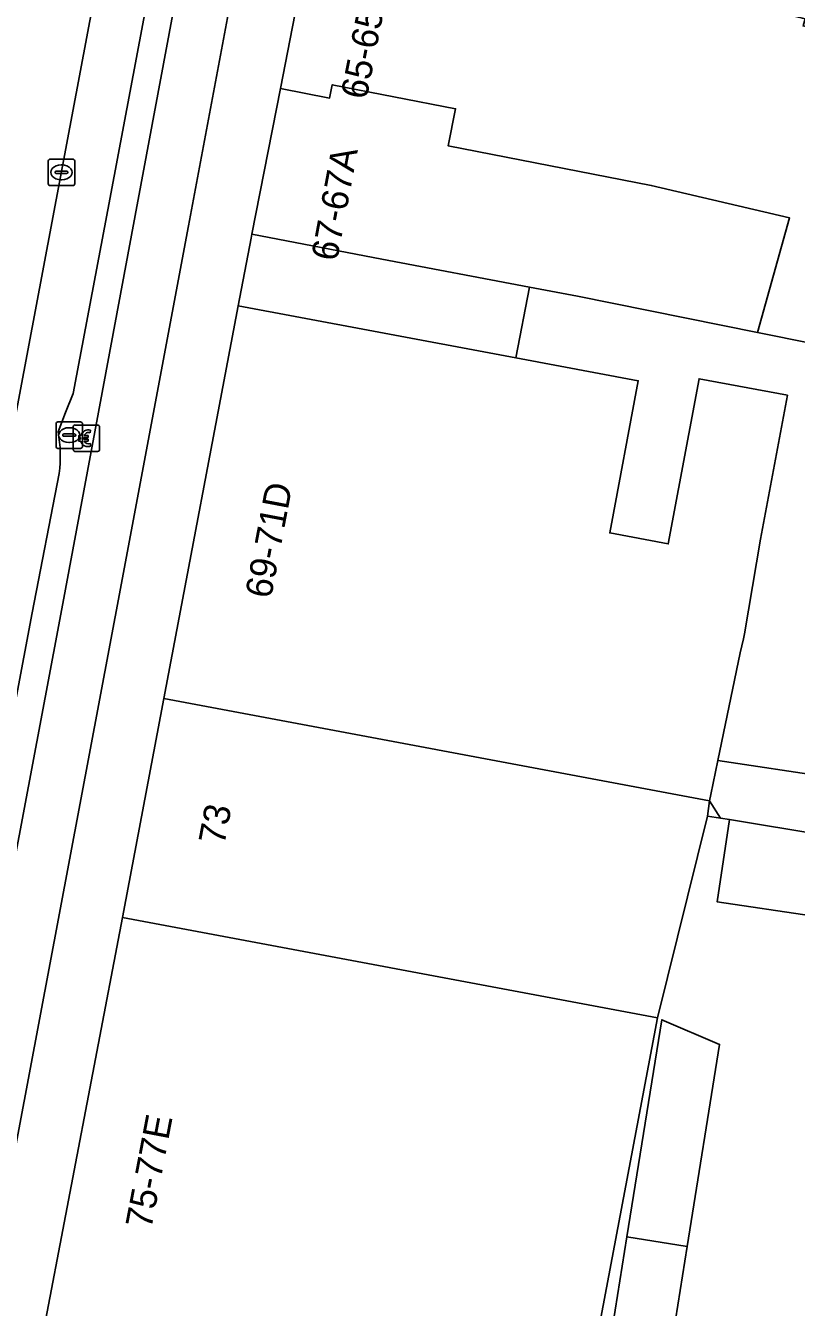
# Model space of a CAD drawing. Extents: x 161838 to 162344, y 381620 to 382160.
# Drawn here: x 161893.72 to 161922.84, y 381857.83 to 381906.27 of the extents above; entities that cross this region are included whole.
import ezdxf

# ---------------------------------------------------------------- set-up
doc = ezdxf.new("R2010")
doc.units = 0
for name, color, linetype in [('IMGEO_Berm_open', 7, 'Continuous'), ('IMGEO_Betaalautomaat', 7, 'Continuous'), ('IMGEO_Brandkraan', 7, 'Continuous'), ('IMGEO_Erf', 7, 'Continuous'), ('IMGEO_Fietspad_gesloten', 7, 'Continuous'), ('IMGEO_Kolk', 7, 'Continuous'), ('IMGEO_Pand', 7, 'Continuous'), ('IMGEO_Pand_nummerreeks', 7, 'Continuous'), ('IMGEO_Pand_overbouw', 7, 'Continuous'), ('IMGEO_Parkeervlak_open', 7, 'Continuous'), ('IMGEO_Rijbaan_lokaal_gesloten', 7, 'Continuous'), ('IMGEO_Voetpad_open', 7, 'Continuous')]:
    doc.layers.add(name, color=color, linetype=linetype)

msp = doc.modelspace()

# ---------------------------------------------------------------- linework, layer by layer
at = {"layer": 'IMGEO_Berm_open'}
for points in [[(161897.858, 381899.101), (161916.698, 382000), (161921.558, 382026.031), (161926.346, 382051.921)], [(161900.616, 381919.482), (161896.821, 381899.305), (161895.517, 381892.371), (161895.218, 381891.646), (161894.941, 381890.914)], [(161857.316, 381682.246), (161862.987, 381712.892), (161864.774, 381722.548), (161869.854, 381750), (161870.207, 381751.91), (161895.081, 381884.229), (161897.858, 381899.101)], [(161894.979, 381889.343), (161893.959, 381884.074), (161881.221, 381816.302), (161880.899, 381815.584)]]:
    msp.add_lwpolyline(points, dxfattribs=at)
msp.add_arc((161890.246, 381890.014), 4.78, 351.925, 10.8462, dxfattribs=at)
at = {"layer": 'IMGEO_Betaalautomaat'}
for p, q in [((161895.511, 381890.252), (161895.511, 381891.093)), ((161895.511, 381891.093), (161895.511, 381890.252)), ((161895.586, 381891.176), (161896.427, 381891.176)), ((161896.427, 381891.176), (161895.586, 381891.176)), ((161896.173, 381890.981), (161896.156, 381890.881)), ((161896.51, 381891.102), (161896.51, 381890.261)), ((161896.51, 381890.261), (161896.51, 381891.102)), ((161895.794, 381890.64), (161895.794, 381890.708)), ((161895.915, 381890.708), (161895.915, 381890.64)), ((161896.16, 381890.475), (161896.182, 381890.388)), ((161896.436, 381890.177), (161895.595, 381890.177)), ((161895.595, 381890.177), (161896.436, 381890.177))]:
    msp.add_line(p, q, dxfattribs=at)
for points in [[(161895.794, 381890.708), (161895.725, 381890.708), (161895.725, 381890.777), (161895.804, 381890.777)], [(161895.799, 381890.571), (161895.725, 381890.571), (161895.725, 381890.64), (161895.794, 381890.64)], [(161895.926, 381890.777), (161896.073, 381890.777), (161896.073, 381890.708), (161895.915, 381890.708)], [(161895.915, 381890.64), (161896.073, 381890.64), (161896.073, 381890.571), (161895.929, 381890.571)]]:
    msp.add_lwpolyline(points, dxfattribs=at)
for centre, radius, start, end in [((161895.589, 381891.099), 0.0779, 92.4484, 184.2845), ((161895.589, 381891.099), 0.0779, 92.4484, 184.2845), ((161896.087, 381890.701), 0.293, 73.014, 165.0139), ((161896.433, 381891.099), 0.0779, 2.4484, 94.2845), ((161896.433, 381891.099), 0.0779, 2.4484, 94.2845), ((161896.06, 381890.626), 0.267, 191.8096, 297.0389), ((161896.093, 381890.714), 0.179, 69.3236, 159.5683), ((161896.093, 381890.641), 0.179, 202.7625, 291.8693), ((161895.589, 381890.255), 0.0779, 182.4484, 274.2845), ((161895.589, 381890.255), 0.0779, 182.4484, 274.2845), ((161896.433, 381890.255), 0.0779, 272.4484, 4.2845), ((161896.433, 381890.255), 0.0779, 272.4484, 4.2845)]:
    msp.add_arc(centre, radius, start, end, dxfattribs=at)
at = {"layer": 'IMGEO_Brandkraan'}
for p, q in [((161894.864, 381890.368), (161894.864, 381891.22)), ((161894.939, 381891.294), (161895.791, 381891.294)), ((161895.352, 381891.074), (161895.377, 381891.074)), ((161895.865, 381891.22), (161895.865, 381890.368)), ((161895.123, 381890.788), (161895.123, 381890.8)), ((161895.561, 381890.751), (161895.163, 381890.751)), ((161895.166, 381890.837), (161895.564, 381890.837)), ((161895.375, 381890.514), (161895.35, 381890.514)), ((161895.607, 381890.8), (161895.607, 381890.788)), ((161895.791, 381890.294), (161894.939, 381890.294))]:
    msp.add_line(p, q, dxfattribs=at)
for points in [[(161894.864, 381890.368), (161894.864, 381891.22)], [(161894.939, 381891.294), (161895.791, 381891.294)], [(161895.865, 381891.22), (161895.865, 381890.368)], [(161895.791, 381890.294), (161894.939, 381890.294)]]:
    msp.add_lwpolyline(points, dxfattribs=at)
for centre, radius, start, end in [((161894.941, 381891.218), 0.0765, 91.552, 178.448), ((161894.941, 381891.218), 0.0765, 91.552, 178.448), ((161895.789, 381891.218), 0.0765, 1.552, 88.448), ((161895.789, 381891.218), 0.0765, 1.552, 88.448), ((161895.163, 381890.797), 0.0403, 85.8775, 175.7526), ((161895.16, 381890.787), 0.0366, 178.938, 274.7102), ((161895.564, 381890.794), 0.043, 264.8664, 352.4533), ((161895.568, 381890.799), 0.0386, 1.7309, 96.639), ((161894.941, 381890.37), 0.0765, 181.552, 268.448), ((161894.941, 381890.37), 0.0765, 181.552, 268.448), ((161895.789, 381890.37), 0.0765, 271.552, 358.448), ((161895.789, 381890.37), 0.0765, 271.552, 358.448)]:
    msp.add_arc(centre, radius, start, end, dxfattribs=at)
for centre, major_axis, ratio, start_param, end_param in [((161895.351, 381890.794), (-0.387, 0.002), 0.722429, 4.712389, 7.853982), ((161895.376, 381890.794), (-0.39, 0.002), 0.717154, 1.570796, 4.712389)]:
    msp.add_ellipse(centre, major_axis=major_axis, ratio=ratio, start_param=start_param, end_param=end_param, dxfattribs=at)
at = {"layer": 'IMGEO_Erf'}
for points in [[(161923.437, 381894.255), (161921.374, 381894.671), (161914.564, 381896.043), (161912.75, 381896.389), (161907.18, 381897.45), (161902.268, 381898.386), (161902.239, 381898.237), (161901.744, 381895.676), (161906.659, 381894.757), (161912.24, 381893.714), (161916.864, 381892.849), (161915.788, 381887.095), (161917.997, 381886.682), (161919.164, 381892.922), (161922.502, 381892.298), (161921.485, 381886.86), (161920.879, 381883.283), (161920.836, 381883.1), (161920.712, 381882.567), (161919.869, 381878.497), (161924.063, 381877.869)], [(161927.341, 381856.208), (161927.586, 381859.394), (161927.862, 381862.975), (161923.927, 381863.278), (161924.192, 381866.576), (161931.915, 381865.948), (161936.898, 381865.542), (161937.059, 381867.638), (161932.115, 381868.378), (161926.43, 381869.229), (161926.861, 381872.114), (161926.008, 381872.241), (161923.414, 381872.627), (161919.842, 381873.159), (161920.308, 381876.262), (161919.974, 381876.316), (161919.486, 381876.396), (161917.589, 381868.765), (161914.902, 381854.491)]]:
    msp.add_lwpolyline(points, dxfattribs=at)
for points in [[(161919.552, 381876.967), (161919.486, 381876.396), (161919.974, 381876.316)], [(161917.918, 381855.141), (161915.635, 381855.508), (161916.435, 381860.485), (161917.755, 381868.694), (161919.938, 381867.762), (161918.709, 381860.12)]]:
    msp.add_lwpolyline(points, close=True, dxfattribs=at)
at = {"layer": 'IMGEO_Fietspad_gesloten'}
for points in [[(161897.095, 381883.929), (161899.866, 381898.705), (161907.39, 381938.834), (161908.427, 381944.469), (161918.786, 382000), (161923.625, 382025.943), (161928.95, 382054.459)], [(161926.346, 382051.921), (161921.558, 382026.031), (161916.698, 382000), (161897.858, 381899.101), (161895.081, 381884.229), (161870.207, 381751.91), (161869.854, 381750), (161864.774, 381722.548), (161862.987, 381712.892), (161857.316, 381682.246)], [(161859.158, 381680.785), (161865.321, 381714.277), (161866.402, 381720.165), (161871.936, 381750), (161872.236, 381751.615), (161897.095, 381883.929)]]:
    msp.add_lwpolyline(points, dxfattribs=at)
at = {"layer": 'IMGEO_Kolk'}
for p, q in [((161894.569, 381900.3), (161894.569, 381901.152)), ((161894.644, 381901.226), (161895.496, 381901.226)), ((161895.57, 381901.152), (161895.57, 381900.3)), ((161894.828, 381900.72), (161894.828, 381900.732)), ((161895.266, 381900.683), (161894.868, 381900.683)), ((161894.871, 381900.769), (161895.269, 381900.769)), ((161895.057, 381901.006), (161895.082, 381901.006)), ((161895.312, 381900.732), (161895.312, 381900.72)), ((161895.496, 381900.226), (161894.644, 381900.226)), ((161895.08, 381900.446), (161895.055, 381900.446))]:
    msp.add_line(p, q, dxfattribs=at)
for points in [[(161894.569, 381900.3), (161894.569, 381901.152)], [(161894.644, 381901.226), (161895.496, 381901.226)], [(161895.57, 381901.152), (161895.57, 381900.3)], [(161895.496, 381900.226), (161894.644, 381900.226)]]:
    msp.add_lwpolyline(points, dxfattribs=at)
for centre, radius, start, end in [((161894.646, 381901.15), 0.0765, 91.552, 178.448), ((161894.646, 381901.15), 0.0765, 91.552, 178.448), ((161895.494, 381901.15), 0.0765, 1.552, 88.448), ((161895.494, 381901.15), 0.0765, 1.552, 88.448), ((161894.868, 381900.729), 0.0403, 85.8775, 175.7526), ((161894.865, 381900.719), 0.0366, 178.938, 274.7102), ((161895.269, 381900.726), 0.043, 264.8664, 352.4533), ((161895.273, 381900.731), 0.0386, 1.7309, 96.639), ((161894.646, 381900.302), 0.0765, 181.552, 268.448), ((161894.646, 381900.302), 0.0765, 181.552, 268.448), ((161895.494, 381900.302), 0.0765, 271.552, 358.448), ((161895.494, 381900.302), 0.0765, 271.552, 358.448)]:
    msp.add_arc(centre, radius, start, end, dxfattribs=at)
for centre, major_axis, ratio, start_param, end_param in [((161895.056, 381900.726), (-0.387, 0.002), 0.722429, 4.712389, 7.853982), ((161895.081, 381900.726), (-0.39, 0.002), 0.717154, 1.570796, 4.712389)]:
    msp.add_ellipse(centre, major_axis=major_axis, ratio=ratio, start_param=start_param, end_param=end_param, dxfattribs=at)
at = {"layer": 'IMGEO_Pand'}
for points in [[(161923.168, 381906.529), (161923.069, 381906.553), (161922.591, 381906.67), (161916.152, 381908.245), (161904.636, 381910.55), (161904.615, 381910.446), (161903.341, 381903.897), (161905.201, 381903.534), (161905.299, 381904.038), (161909.961, 381903.128), (161909.687, 381901.727), (161917.356, 381900.23), (161922.583, 381899.012), (161921.374, 381894.671), (161923.437, 381894.255), (161924.39, 381897.931), (161925.021, 381900.361), (161925.851, 381903.561), (161926.341, 381905.451), (161923.093, 381906.261)], [(161903.341, 381903.897), (161902.268, 381898.386), (161907.18, 381897.45), (161912.75, 381896.389), (161914.564, 381896.043), (161921.374, 381894.671), (161922.583, 381899.012), (161917.356, 381900.23), (161909.687, 381901.727), (161909.961, 381903.128), (161905.299, 381904.038), (161905.201, 381903.534)], [(161916.864, 381892.849), (161912.24, 381893.714), (161906.659, 381894.757), (161901.744, 381895.676), (161898.938, 381880.835), (161919.552, 381876.967), (161919.603, 381877.215), (161919.869, 381878.497), (161920.712, 381882.567), (161920.836, 381883.1), (161920.879, 381883.283), (161921.485, 381886.86), (161922.502, 381892.298), (161919.164, 381892.922), (161917.997, 381886.682), (161915.788, 381887.095)], [(161919.869, 381878.497), (161919.603, 381877.215), (161919.552, 381876.967), (161919.974, 381876.316), (161920.308, 381876.262), (161923.872, 381875.678), (161926.464, 381875.29), (161937.91, 381873.639), (161938.852, 381880.284), (161929.808, 381881.571), (161929.749, 381881.177), (161929.642, 381880.46), (161929.229, 381877.704), (161924.153, 381878.464), (161924.063, 381877.869)], [(161897.372, 381872.555), (161917.589, 381868.765), (161919.486, 381876.396), (161919.552, 381876.967), (161898.938, 381880.835)], [(161923.872, 381875.678), (161920.308, 381876.262), (161919.842, 381873.159), (161923.414, 381872.627)], [(161917.589, 381868.765), (161897.372, 381872.555), (161894.318, 381856.539), (161914.574, 381852.746), (161914.848, 381854.2), (161914.902, 381854.491)], [(161916.435, 381860.485), (161918.709, 381860.12), (161919.938, 381867.762), (161917.755, 381868.694)], [(161918.709, 381860.12), (161916.435, 381860.485), (161915.635, 381855.508), (161917.918, 381855.141)]]:
    msp.add_lwpolyline(points, close=True, dxfattribs=at)
at = {"layer": 'IMGEO_Pand_overbouw'}
msp.add_lwpolyline([(161912.75, 381896.389), (161907.18, 381897.45), (161902.268, 381898.386), (161902.239, 381898.237), (161901.744, 381895.676), (161906.659, 381894.757), (161912.24, 381893.714)], close=True, dxfattribs=at)
at = {"layer": 'IMGEO_Parkeervlak_open'}
for points in [[(161899.202, 381922.742), (161894.868, 381899.69), (161871.456, 381775.156)], [(161894.941, 381890.914), (161895.218, 381891.646), (161895.517, 381892.371), (161896.821, 381899.305), (161900.616, 381919.482)], [(161880.899, 381815.584), (161881.221, 381816.302), (161893.959, 381884.074), (161894.979, 381889.343)]]:
    msp.add_lwpolyline(points, dxfattribs=at)
msp.add_arc((161890.246, 381890.014), 4.78, 351.925, 10.8462, dxfattribs=at)
at = {"layer": 'IMGEO_Rijbaan_lokaal_gesloten'}
msp.add_lwpolyline([(161862.533, 381727.211), (161866.175, 381746.944), (161866.739, 381750), (161866.904, 381750.735), (161870.759, 381771.481), (161871.456, 381775.156), (161894.868, 381899.69), (161899.202, 381922.742), (161901.082, 381932.662), (161902.001, 381937.624), (161903.787, 381947.27), (161904.686, 381952.125), (161905.076, 381954.299), (161905.11, 381954.479), (161913.622, 382000), (161917.608, 382021.312), (161917.651, 382021.542), (161920.351, 382034.502), (161920.367, 382034.753)], dxfattribs=at)
at = {"layer": 'IMGEO_Voetpad_open'}
for points in [[(161901.744, 381895.676), (161902.239, 381898.237), (161902.268, 381898.386), (161903.341, 381903.897), (161904.615, 381910.446), (161904.636, 381910.55), (161908.231, 381929.021), (161909.255, 381934.284), (161909.938, 381934.153), (161910.655, 381938.724), (161910.232, 381938.9), (161910.088, 381938.932)], [(161907.39, 381938.834), (161899.866, 381898.705), (161897.095, 381883.929), (161872.236, 381751.615), (161871.936, 381750), (161866.402, 381720.165)], [(161868.609, 381718.629), (161868.92, 381722.091), (161872.827, 381742.933), (161873.489, 381746.458), (161874.307, 381746.749), (161874.727, 381749.038), (161874.078, 381749.589), (161874.155, 381750), (161875.101, 381755.029), (161876.159, 381760.654), (161877.48, 381767.677), (161880.122, 381781.461), (161880.152, 381781.62), (161881.558, 381789.042), (161882.7, 381795.067), (161887.08, 381818.184), (161887.141, 381818.507), (161891.353, 381840.988), (161894.318, 381856.539), (161897.372, 381872.555), (161898.938, 381880.835), (161901.744, 381895.676)]]:
    msp.add_lwpolyline(points, dxfattribs=at)

# ---------------------------------------------------------------- texts
at = {"layer": 'IMGEO_Pand_nummerreeks'}
for s, rotation, p in [('65-65A', 78.988, (161906.596, 381903.448)), ('67-67A', 79.4521, (161905.482, 381897.334)), ('69-71D', 79.2916, (161902.986, 381884.585)), ('73', 79.2901, (161901.224, 381875.274)), ('75-77E', 79.2057, (161898.463, 381860.761))]:
    msp.add_text(s, height=1, rotation=rotation, dxfattribs=at).set_placement(p)

doc.saveas('drawing.dxf')
